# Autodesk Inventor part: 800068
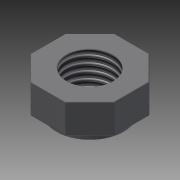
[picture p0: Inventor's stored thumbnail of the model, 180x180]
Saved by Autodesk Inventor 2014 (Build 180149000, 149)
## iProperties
Created: 2007-11
Part Number: 800068
Document SubType Name: Modeling
Designer: TH
Density: 8.08 g/cm^3
Mass: 11.8468 g
Surface Area: 11.3549 cm^2
Volume: 1.46619 cm^3
Material: Stainless Steel
Description: N34 NUT M12
Appearance: Light Gray
Component Category: Fasteners
Author: TH
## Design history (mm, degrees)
sketch "Sketch1"
  geometry: L1 (-12.805, 0)-(12.805, 0) reference; L2 (9.147, -3.789)-(3.789, -9.147); L3 (3.789, -9.147)-(-3.789, -9.147); L4 (-3.789, -9.147)-(-9.146, -3.789); L5 (-9.146, -3.789)-(-9.146, 3.789); L6 (-9.146, 3.789)-(-3.789, 9.146); L7 (-3.789, 9.146)-(3.789, 9.146); L8 (3.789, 9.146)-(9.146, 3.789); L9 (9.146, 3.789)-(9.147, -3.789); C1 r 5 at (0, 0); 3 further points
  constraints: 16 end point, 2 coincident, 1 centre point, 1 midpoint, 1 point on line, 17 other
  dimensions: "d0" = 18.293 distance between parallel lines of L9 L5; "d1" = 10 diameter of C1
extrude "Extrusion1" new body sketch "Sketch1" distance "d2" = 6.48; taper "d3" = 0 deg
sketch "Sketch2"
  geometry: C1 r 5 at (0, 0) reference; C2 r 7.325 at (0, 0)
  constraints: 1 centre point, 1 coincident
  dimensions: "d4" = 14.65 diameter of C2
extrude "Extrusion2" join sketch "Sketch2" distance "d5" = 2; taper "d6" = 0 deg
fillet "Fillet1" dims "d7" = 0.2
thread "Thread1" dims "d8" = 10, "d9" = 0
body "Solid1"
